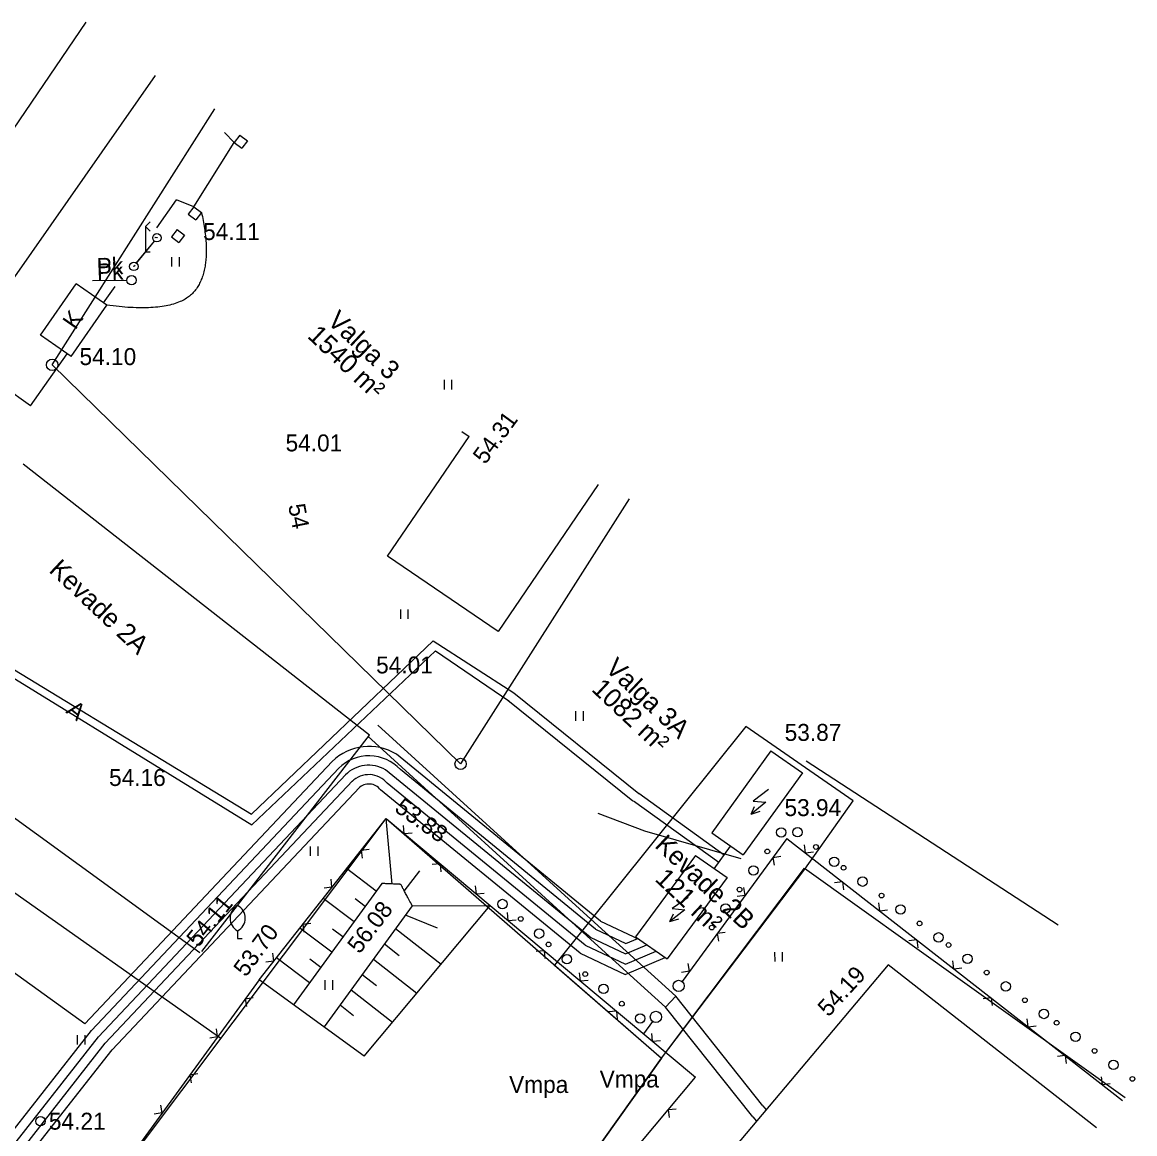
# Model space of a CAD drawing. Extents: x -2270 to -2134, y 846 to 969.
# Drawn here: x -2193 to -2133.9, y 905.2 to 964.2 of the extents above; entities that cross this region are included whole.
import ezdxf

# ---------------------------------------------------------------- set-up
doc = ezdxf.new("R2010")
doc.units = 0
for name, color, linetype in [('Level 10', 7, 'Continuous'), ('Level 12', 7, 'Continuous'), ('Level 15', 7, 'Continuous'), ('Level 19', 7, 'Continuous'), ('Level 21', 7, 'Continuous'), ('Level 32', 7, 'Continuous'), ('Level 4', 7, 'Continuous'), ('Level 45', 7, 'Continuous'), ('Level 6', 7, 'Continuous'), ('Level 63', 7, 'Continuous'), ('Level 7', 7, 'Continuous'), ('Level 8', 7, 'Continuous'), ('Level 9', 7, 'Continuous')]:
    doc.layers.add(name, color=color, linetype=linetype)

# ---------------------------------------------------------------- blocks, each defined once
blk = doc.blocks.new('37')
at = {"layer": 'Level 63'}
blk.add_line((0, 0), (0, 0), dxfattribs=at)
for centre, radius in [((0.0004, 0.2501), 0.005), ((0.0004, 0.2001), 0.01), ((0.0003, 0.1501), 0.005), ((0.0002, 0.1001), 0.01), ((0.0001, 0.05), 0.005), ((0, 0), 0.01)]:
    blk.add_circle(centre, radius, dxfattribs=at)
blk = doc.blocks.new('HAKA')
at = {"layer": 'Level 63'}
for q in [(-0.012, 0.012), (0.012, 0.012)]:
    blk.add_line((0, 0), q, dxfattribs=at)

msp = doc.modelspace()

# ---------------------------------------------------------------- linework, layer by layer
at = {"layer": 'Level 10'}
for p, q in [((-2181.4, 958.241), (-2181.701, 957.842)), ((-2181.4, 958.241), (-2181.001, 957.94)), ((-2181.701, 957.842), (-2181.302, 957.541)), ((-2181.001, 957.94), (-2181.302, 957.541)), ((-2183.838, 954.437), (-2184.139, 954.038)), ((-2183.838, 954.437), (-2183.439, 954.136)), ((-2183.439, 954.136), (-2183.74, 953.737)), ((-2184.139, 954.038), (-2183.74, 953.737)), ((-2184.739, 953.232), (-2185.04, 952.833)), ((-2184.739, 953.232), (-2184.34, 952.931)), ((-2184.34, 952.931), (-2184.641, 952.532)), ((-2185.04, 952.833), (-2184.641, 952.532)), ((-2180.377, 913.395), (-2173.638, 921.957)), ((-2173.638, 921.957), (-2168.115, 917.339)), ((-2172.679, 921.155), (-2172.717, 921.578)), ((-2172.679, 921.155), (-2172.257, 921.193)), ((-2152.352, 920.896), (-2157.922, 913.305)), ((-2152.352, 920.896), (-2134.526, 906.987)), ((-2151.366, 920.127), (-2151.418, 920.548)), ((-2174.965, 920.271), (-2174.544, 920.321)), ((-2174.965, 920.271), (-2174.915, 919.849)), ((-2153.091, 919.888), (-2152.672, 919.953)), ((-2153.091, 919.888), (-2153.027, 919.469)), ((-2151.366, 920.127), (-2150.945, 920.179)), ((-2170.761, 919.552), (-2171.184, 919.514)), ((-2170.761, 919.552), (-2170.724, 919.129)), ((-2176.512, 918.306), (-2176.562, 918.727)), ((-2176.512, 918.306), (-2176.933, 918.256)), ((-2168.843, 917.948), (-2168.881, 918.371)), ((-2154.57, 917.873), (-2154.635, 918.292)), ((-2149.395, 918.589), (-2149.817, 918.537)), ((-2149.395, 918.589), (-2149.344, 918.168)), ((-2168.843, 917.948), (-2168.421, 917.986)), ((-2154.57, 917.873), (-2154.99, 917.808)), ((-2168.115, 917.339), (-2162.369, 912.535)), ((-2167.156, 916.537), (-2167.194, 916.96)), ((-2178.058, 916.342), (-2177.637, 916.392)), ((-2178.058, 916.342), (-2178.008, 915.92)), ((-2167.156, 916.537), (-2166.734, 916.575)), ((-2156.049, 915.857), (-2155.63, 915.922)), ((-2156.049, 915.857), (-2155.985, 915.438)), ((-2179.604, 914.377), (-2179.655, 914.798)), ((-2165.238, 914.934), (-2165.661, 914.896)), ((-2165.238, 914.934), (-2165.201, 914.511)), ((-2179.604, 914.377), (-2180.026, 914.327)), ((-2157.528, 913.842), (-2157.593, 914.261)), ((-2180.377, 913.395), (-2188.744, 901.892)), ((-2163.32, 913.33), (-2163.358, 913.753)), ((-2163.32, 913.33), (-2162.898, 913.368)), ((-2157.528, 913.842), (-2157.948, 913.777)), ((-2181.113, 912.384), (-2180.694, 912.45)), ((-2181.113, 912.384), (-2181.047, 911.965)), ((-2162.369, 912.535), (-2157.213, 908.223)), ((-2161.403, 911.727), (-2161.826, 911.689)), ((-2161.403, 911.727), (-2161.365, 911.304)), ((-2159.483, 911.177), (-2159.963, 910.523)), ((-2182.583, 910.363), (-2182.65, 910.782)), ((-2159.485, 910.123), (-2159.523, 910.545)), ((-2182.583, 910.363), (-2183.003, 910.297)), ((-2159.485, 910.123), (-2159.062, 910.16)), ((-2184.054, 908.341), (-2183.635, 908.407)), ((-2184.054, 908.341), (-2183.988, 907.922)), ((-2162.369, 902.057), (-2157.213, 908.223)), ((-2185.524, 906.319), (-2185.944, 906.253)), ((-2185.524, 906.319), (-2185.591, 906.738))]:
    msp.add_line(p, q, dxfattribs=at)
for centre in [(-2158.1, 913.063), (-2159.306, 911.419)]:
    msp.add_circle(centre, 0.3, dxfattribs=at)
at = {"layer": 'Level 12'}
for p, q in [((-2186.162, 953.636), (-2186.412, 953.385)), ((-2186.412, 953.385), (-2186.413, 952.028)), ((-2186.412, 953.385), (-2186.162, 953.136)), ((-2186.896, 951.451), (-2185.93, 952.605)), ((-2185.817, 952.794), (-2185.907, 952.802)), ((-2186.163, 952.028), (-2186.413, 952.028)), ((-2187.024, 951.278), (-2186.958, 951.339)), ((-2187.4, 950.529), (-2189.222, 950.496))]:
    msp.add_line(p, q, dxfattribs=at)
for centre, radius in [((-2185.907, 952.802), 0.005), ((-2185.807, 952.793), 0.01), ((-2187.031, 951.271), 0.01), ((-2186.958, 951.339), 0.005), ((-2187.15, 950.533), 0.25), ((-2191.993, 905.88), 0.25), ((-2191.993, 905.88), 0.25)]:
    msp.add_circle(centre, radius, dxfattribs=at)
at = {"layer": 'Level 15'}
for p, q in [((-2181.4, 958.241), (-2181.701, 957.842)), ((-2181.4, 958.241), (-2181.001, 957.94)), ((-2181.701, 957.842), (-2181.302, 957.541)), ((-2181.001, 957.94), (-2181.302, 957.541)), ((-2183.838, 954.437), (-2184.139, 954.038)), ((-2183.838, 954.437), (-2183.439, 954.136)), ((-2183.439, 954.136), (-2183.74, 953.737)), ((-2184.139, 954.038), (-2183.74, 953.737)), ((-2184.739, 953.232), (-2185.04, 952.833)), ((-2184.739, 953.232), (-2184.34, 952.931)), ((-2184.34, 952.931), (-2184.641, 952.532)), ((-2185.04, 952.833), (-2184.641, 952.532))]:
    msp.add_line(p, q, dxfattribs=at)
msp.add_lwpolyline([(-2238.128, 896.128), (-2210.494, 933.465), (-2189.567, 964.235)], dxfattribs=at)
at = {"layer": 'Level 19'}
for p, q in [((-2185.903, 961.405), (-2197.926, 944.224)), ((-2174.518, 926.382), (-2192.902, 940.765)), ((-2167.174, 928.244), (-2160.529, 922.892)), ((-2166.861, 928.633), (-2160.215, 923.282)), ((-2183.428, 914.895), (-2174.518, 926.382)), ((-2155.967, 919.609), (-2160.507, 922.876)), ((-2155.675, 920.015), (-2160.215, 923.282)), ((-2156.206, 919.278), (-2155.348, 920.479))]:
    msp.add_line(p, q, dxfattribs=at)
for points in [[(-2197.783, 932.526), (-2180.783, 922.176), (-2171.133, 931.391), (-2166.861, 928.633)], [(-2197.901, 932.165), (-2180.774, 921.614), (-2171.008, 930.85), (-2167.125, 928.209)]]:
    msp.add_lwpolyline(points, dxfattribs=at)
at = {"layer": 'Level 21'}
for p, q in [((-2162.256, 916.501), (-2173.084, 925.363)), ((-2189.64, 911.045), (-2176.503, 924.978)), ((-2189.276, 910.702), (-2176.139, 924.635)), ((-2151.337, 925.021), (-2137.95, 916.314)), ((-2188.912, 910.359), (-2175.776, 924.292)), ((-2162.793, 915.648), (-2173.662, 924.544)), ((-2162.525, 916.075), (-2172.879, 924.549)), ((-2188.549, 910.016), (-2175.412, 923.949)), ((-2188.185, 909.673), (-2175.048, 923.606)), ((-2163.329, 914.795), (-2173.933, 923.474)), ((-2163.061, 915.222), (-2173.575, 923.827)), ((-2189.64, 911.045), (-2200.158, 918.652)), ((-2162.256, 916.501), (-2160.221, 915.551)), ((-2162.525, 916.075), (-2160.908, 915.32)), ((-2163.061, 915.222), (-2160.93, 914.226)), ((-2162.793, 915.648), (-2160.919, 914.773)), ((-2160.919, 914.773), (-2159.788, 915.249)), ((-2160.908, 915.32), (-2160.273, 915.587)), ((-2163.329, 914.795), (-2160.94, 913.679)), ((-2160.94, 913.679), (-2158.81, 914.575)), ((-2160.93, 914.226), (-2159.303, 914.91)), ((-2208.173, 886.648), (-2189.276, 910.702)), ((-2207.864, 886.227), (-2188.912, 910.359)), ((-2207.466, 885.925), (-2188.549, 910.016)), ((-2207.068, 885.622), (-2188.185, 909.673))]:
    msp.add_line(p, q, dxfattribs=at)
for radius, start in [(2.77, 58.03691), (2.27, 42.59346), (1.77, 59.88305), (1.27, 39.85548), (0.77, 36.76007)]:
    msp.add_arc((-2174.55, 923.013), radius, start, 134.82374, dxfattribs=at)
at = {"layer": 'Level 32'}
msp.add_lwpolyline([(-2154.788, 919.816), (-2159.894, 921.281), (-2162.369, 922.212)], dxfattribs=at)
at = {"layer": 'Level 45'}
for p, q in [((-2169.679, 924.854), (-2191.369, 946.044)), ((-2206.455, 927.192), (-2182.404, 910.289)), ((-2154.541, 926.833), (-2164.685, 914.164)), ((-2148.828, 922.892), (-2154.541, 926.833)), ((-2151.398, 919.271), (-2148.828, 922.892)), ((-2195.519, 892.834), (-2173.639, 921.954)), ((-2173.639, 921.954), (-2159.019, 909.234)), ((-2159.019, 909.234), (-2151.409, 919.324)), ((-2159.019, 909.234), (-2151.398, 919.271)), ((-2151.409, 919.324), (-2134.388, 907.134)), ((-2164.685, 914.164), (-2159.019, 909.234)), ((-2159.019, 909.234), (-2173.879, 888.284)), ((-2173.879, 888.284), (-2159.019, 909.234))]:
    msp.add_line(p, q, dxfattribs=at)
msp.add_lwpolyline([(-2160.73, 938.925), (-2169.68, 924.85), (-2191.369, 946.044), (-2182.733, 959.637)], dxfattribs=at)
for centre in [(-2191.369, 946.044), (-2169.679, 924.854)]:
    msp.add_circle(centre, 0.3, dxfattribs=at)
at = {"layer": 'Level 6'}
for p, q in [((-2191.989, 947.614), (-2190.091, 950.35)), ((-2188.47, 949.216), (-2190.091, 950.35)), ((-2190.368, 946.48), (-2188.47, 949.216)), ((-2190.368, 946.48), (-2191.989, 947.614)), ((-2169.608, 942.508), (-2169.223, 942.245)), ((-2173.556, 935.889), (-2169.223, 942.245)), ((-2162.369, 939.685), (-2167.68, 931.887)), ((-2167.68, 931.887), (-2173.556, 935.889)), ((-2153.201, 925.548), (-2156.346, 921.188)), ((-2153.201, 925.548), (-2156.346, 921.188)), ((-2153.201, 925.548), (-2156.346, 921.188)), ((-2153.201, 925.548), (-2156.346, 921.188)), ((-2153.201, 925.548), (-2151.525, 924.378)), ((-2153.201, 925.548), (-2151.525, 924.378)), ((-2153.201, 925.548), (-2151.525, 924.378)), ((-2153.201, 925.548), (-2151.525, 924.378)), ((-2151.525, 924.378), (-2154.67, 920.018)), ((-2151.525, 924.378), (-2154.67, 920.018)), ((-2151.525, 924.378), (-2154.67, 920.018)), ((-2151.525, 924.378), (-2154.67, 920.018)), ((-2153.324, 923.498), (-2154.139, 922.872)), ((-2153.324, 923.498), (-2154.139, 922.872)), ((-2153.324, 923.498), (-2154.139, 922.872)), ((-2153.324, 923.498), (-2154.139, 922.872)), ((-2153.472, 922.83), (-2154.252, 922.189)), ((-2153.472, 922.83), (-2154.252, 922.189)), ((-2153.472, 922.83), (-2154.252, 922.189)), ((-2153.472, 922.83), (-2154.252, 922.189)), ((-2154.139, 922.872), (-2153.472, 922.83)), ((-2154.139, 922.872), (-2153.472, 922.83)), ((-2154.139, 922.872), (-2153.472, 922.83)), ((-2154.139, 922.872), (-2153.472, 922.83)), ((-2154.252, 922.189), (-2154.07, 922.593)), ((-2154.252, 922.189), (-2154.07, 922.593)), ((-2154.252, 922.189), (-2154.07, 922.593)), ((-2154.252, 922.189), (-2154.07, 922.593)), ((-2154.252, 922.189), (-2153.779, 922.338)), ((-2154.252, 922.189), (-2153.779, 922.338)), ((-2154.252, 922.189), (-2153.779, 922.338)), ((-2154.252, 922.189), (-2153.779, 922.338)), ((-2156.346, 921.188), (-2154.67, 920.018)), ((-2156.346, 921.188), (-2154.67, 920.018)), ((-2156.346, 921.188), (-2154.67, 920.018)), ((-2156.346, 921.188), (-2154.67, 920.018)), ((-2157.204, 919.987), (-2160.389, 915.664)), ((-2157.204, 919.987), (-2160.389, 915.664)), ((-2157.204, 919.987), (-2160.389, 915.664)), ((-2157.204, 919.987), (-2160.389, 915.664)), ((-2157.204, 919.987), (-2155.528, 918.817)), ((-2157.204, 919.987), (-2155.528, 918.817)), ((-2157.204, 919.987), (-2155.528, 918.817)), ((-2157.204, 919.987), (-2155.528, 918.817)), ((-2155.528, 918.817), (-2158.713, 914.494)), ((-2155.528, 918.817), (-2158.713, 914.494)), ((-2155.528, 918.817), (-2158.713, 914.494)), ((-2155.528, 918.817), (-2158.713, 914.494)), ((-2157.602, 917.764), (-2158.439, 917.169)), ((-2157.602, 917.764), (-2158.439, 917.169)), ((-2157.602, 917.764), (-2158.439, 917.169)), ((-2157.602, 917.764), (-2158.439, 917.169)), ((-2157.774, 917.103), (-2158.577, 916.49)), ((-2157.774, 917.103), (-2158.577, 916.49)), ((-2157.774, 917.103), (-2158.577, 916.49)), ((-2157.774, 917.103), (-2158.577, 916.49)), ((-2158.577, 916.49), (-2158.381, 916.887)), ((-2158.577, 916.49), (-2158.381, 916.887)), ((-2158.577, 916.49), (-2158.381, 916.887)), ((-2158.577, 916.49), (-2158.381, 916.887)), ((-2158.439, 917.169), (-2157.774, 917.103)), ((-2158.439, 917.169), (-2157.774, 917.103)), ((-2158.439, 917.169), (-2157.774, 917.103)), ((-2158.439, 917.169), (-2157.774, 917.103)), ((-2158.577, 916.49), (-2158.099, 916.621)), ((-2158.577, 916.49), (-2158.099, 916.621)), ((-2158.577, 916.49), (-2158.099, 916.621)), ((-2158.577, 916.49), (-2158.099, 916.621)), ((-2160.389, 915.664), (-2158.713, 914.494)), ((-2160.389, 915.664), (-2158.713, 914.494)), ((-2160.389, 915.664), (-2158.713, 914.494)), ((-2160.389, 915.664), (-2158.713, 914.494))]:
    msp.add_line(p, q, dxfattribs=at)
at = {"layer": 'Level 63'}
for p, q in [((-2149.84, 919.654), (-2149.84, 919.654)), ((-2149.84, 919.654), (-2149.84, 919.654)), ((-2149.84, 919.654), (-2149.84, 919.654)), ((-2149.84, 919.654), (-2149.84, 919.654)), ((-2165.51, 915.841), (-2165.51, 915.841)), ((-2160.144, 911.336), (-2160.144, 911.336))]:
    msp.add_line(p, q, dxfattribs=at)
at = {"layer": 'Level 7'}
for p, q in [((-2181.701, 957.842), (-2182.216, 958.379)), ((-2183.838, 954.437), (-2181.701, 957.842)), ((-2185.818, 953.312), (-2184.761, 954.8)), ((-2183.838, 954.437), (-2184.761, 954.8)), ((-2188.643, 949.337), (-2188.025, 950.207)), ((-2192.525, 943.875), (-2190.572, 946.623)), ((-2192.525, 943.875), (-2193.951, 944.887)), ((-2183.528, 914.813), (-2204.489, 930.045)), ((-2162.369, 916.261), (-2174.073, 926.911)), ((-2162.369, 915.18), (-2174.611, 926.319)), ((-2158.257, 912.52), (-2162.369, 916.261)), ((-2158.796, 911.928), (-2162.369, 915.18)), ((-2146.968, 914.186), (-2157.904, 901.206)), ((-2135.904, 905.524), (-2146.968, 914.186)), ((-2158.257, 912.52), (-2158.796, 911.928)), ((-2153.626, 906.702), (-2158.257, 912.52)), ((-2154.164, 906.11), (-2158.796, 911.928)), ((-2153.626, 906.702), (-2153.453, 906.489)), ((-2154.164, 906.11), (-2153.966, 905.88))]:
    msp.add_line(p, q, dxfattribs=at)
msp.add_open_spline([(-2183.439, 954.136), (-2182.792, 951.215), (-2184.823, 948.705), (-2188.47, 949.216)], degree=2, dxfattribs=at)
at = {"layer": 'Level 8'}
for p, q in [((-2186.162, 953.635), (-2186.412, 953.385)), ((-2186.412, 953.385), (-2186.413, 952.028)), ((-2186.412, 953.385), (-2186.163, 953.135)), ((-2186.897, 951.452), (-2185.93, 952.605)), ((-2186.163, 952.028), (-2186.413, 952.028)), ((-2187.4, 950.529), (-2189.222, 950.496))]:
    msp.add_line(p, q, dxfattribs=at)
for centre, radius in [((-2185.807, 952.793), 0.225), ((-2187.031, 951.271), 0.225), ((-2187.15, 950.533), 0.25), ((-2191.993, 905.88), 0.25)]:
    msp.add_circle(centre, radius, dxfattribs=at)
at = {"layer": 'Level 9'}
for p, q in [((-2185.016, 951.263), (-2185.016, 951.763)), ((-2184.616, 951.263), (-2184.616, 951.763)), ((-2170.543, 944.74), (-2170.543, 945.24)), ((-2170.143, 944.74), (-2170.143, 945.24)), ((-2172.859, 932.556), (-2172.859, 933.056)), ((-2172.459, 932.556), (-2172.459, 933.056)), ((-2163.561, 927.148), (-2163.561, 927.648)), ((-2163.161, 927.148), (-2163.161, 927.648)), ((-2173.309, 918.461), (-2173.638, 921.957)), ((-2152.654, 921.213), (-2152.654, 921.213)), ((-2177.651, 919.968), (-2177.651, 920.468)), ((-2177.251, 919.968), (-2177.251, 920.468)), ((-2174.16, 918.096), (-2175.737, 919.29)), ((-2171.86, 919.17), (-2172.694, 918.088)), ((-2173.865, 918.502), (-2178.547, 912.064)), ((-2175.34, 916.474), (-2176.978, 917.714)), ((-2174.75, 917.285), (-2175.286, 917.691)), ((-2172.247, 917.325), (-2176.93, 910.888)), ((-2174.803, 909.341), (-2168.115, 917.339)), ((-2172.259, 917.31), (-2168.115, 917.339)), ((-2170.9, 916.133), (-2172.608, 916.829)), ((-2181.52, 915.983), (-2181.519, 915.581)), ((-2176.52, 914.852), (-2178.219, 916.138)), ((-2175.93, 915.663), (-2176.486, 916.084)), ((-2173.132, 916.109), (-2170.719, 914.225)), ((-2181.519, 915.581), (-2181.279, 915.581)), ((-2173.722, 915.297), (-2172.936, 914.684)), ((-2177.7, 913.229), (-2179.46, 914.561)), ((-2152.981, 914.358), (-2152.99, 914.858)), ((-2152.581, 914.364), (-2152.59, 914.864)), ((-2177.11, 914.04), (-2177.686, 914.477)), ((-2174.312, 914.486), (-2172.006, 912.686)), ((-2174.803, 909.341), (-2180.377, 913.395)), ((-2176.869, 912.862), (-2176.869, 913.362)), ((-2176.469, 912.862), (-2176.469, 913.362)), ((-2174.902, 913.675), (-2174.151, 913.089)), ((-2175.492, 912.864), (-2173.292, 911.147)), ((-2176.082, 912.053), (-2175.367, 911.495)), ((-2160.144, 911.336), (-2160.144, 911.336)), ((-2190.02, 909.952), (-2190.02, 910.452)), ((-2189.62, 909.952), (-2189.62, 910.452))]:
    msp.add_line(p, q, dxfattribs=at)
for centre, radius in [((-2152.654, 921.213), 0.25), ((-2151.784, 921.228), 0.25), ((-2151.784, 921.228), 0.25), ((-2151.784, 921.228), 0.25), ((-2151.784, 921.228), 0.25), ((-2150.812, 920.441), 0.125), ((-2150.812, 920.441), 0.125), ((-2150.812, 920.441), 0.125), ((-2150.812, 920.441), 0.125), ((-2153.392, 920.203), 0.125), ((-2149.84, 919.654), 0.25), ((-2149.84, 919.654), 0.25), ((-2149.84, 919.654), 0.25), ((-2149.84, 919.654), 0.25), ((-2154.13, 919.193), 0.25), ((-2154.867, 918.183), 0.125), ((-2167.457, 917.412), 0.25), ((-2155.605, 917.173), 0.25), ((-2166.483, 916.626), 0.125), ((-2165.51, 915.84), 0.25), ((-2156.343, 916.163), 0.125), ((-2165.011, 915.264), 0.125), ((-2164.037, 914.478), 0.25), ((-2163.064, 913.692), 0.125), ((-2162.091, 912.907), 0.25), ((-2162.091, 912.907), 0.25), ((-2161.118, 912.121), 0.125), ((-2161.118, 912.121), 0.125), ((-2160.145, 911.336), 0.25), ((-2160.144, 911.336), 0.25), ((-2138.027, 911.105), 0.125), ((-2138.027, 911.105), 0.125), ((-2138.027, 911.105), 0.125), ((-2138.027, 911.105), 0.125), ((-2137.021, 910.361), 0.25), ((-2137.021, 910.361), 0.25), ((-2137.021, 910.361), 0.25), ((-2137.021, 910.361), 0.25), ((-2136.016, 909.616), 0.125), ((-2136.016, 909.616), 0.125), ((-2136.016, 909.616), 0.125), ((-2136.016, 909.616), 0.125), ((-2135.011, 908.872), 0.25), ((-2135.011, 908.872), 0.25), ((-2135.011, 908.872), 0.25), ((-2135.011, 908.872), 0.25), ((-2134.005, 908.128), 0.125), ((-2134.005, 908.128), 0.125), ((-2134.005, 908.128), 0.125), ((-2134.005, 908.128), 0.125)]:
    msp.add_circle(centre, radius, dxfattribs=at)
for centre, start, end in [((-2181.162, 916.658), 118.07128, 242.07104), ((-2181.879, 916.657), 298.07128, 62.07104)]:
    msp.add_arc(centre, 0.763, start, end, dxfattribs=at)
msp.add_open_spline([(-2172.247, 917.325), (-2172.857, 918.456), (-2172.857, 918.456), (-2173.865, 918.502)], degree=2, dxfattribs=at)

# ---------------------------------------------------------------- block references
at = {"layer": 'Level 10', "xscale": 25, "yscale": 25}
for p, rotation in [((-2147.424, 917.051), -37.9647), ((-2145.453, 915.513), 142.03530000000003), ((-2143.482, 913.976), -37.9647), ((-2141.511, 912.438), 142.03530000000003), ((-2139.54, 910.9), -37.9647), ((-2137.569, 909.362), 142.03530000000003), ((-2135.598, 907.824), -37.9647), ((-2158.649, 906.506), -129.90060000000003)]:
    msp.add_blockref('HAKA', p, dxfattribs=dict(at, rotation=rotation))
at = {"layer": 'Level 9', "xscale": 25}
for p, yscale, rotation in [((-2144.3, 915.642), 25, 53.85576208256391), ((-2144.3, 915.642), 25, 53.85576208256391), ((-2144.3, 915.642), 25, 53.85576208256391), ((-2144.3, 915.642), 25, 53.85576208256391), ((-2138.703, 911.574), 24.999999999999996, 54.23280976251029), ((-2138.703, 911.574), 24.999999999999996, 54.23280976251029), ((-2138.703, 911.574), 24.999999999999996, 54.23280976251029), ((-2138.703, 911.574), 24.999999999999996, 54.23280976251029)]:
    msp.add_blockref('37', p, dxfattribs=dict(at, yscale=yscale, rotation=rotation))

# ---------------------------------------------------------------- texts
at = {"layer": 'Level 12'}
msp.add_text('Pk', height=0.9, rotation=2, dxfattribs=at).set_placement((-2188.988, 950.811))
at = {"layer": 'Level 32'}
msp.add_text('54', height=0.9, rotation=281, dxfattribs=at).set_placement((-2178.841, 938.581))
at = {"layer": 'Level 4'}
for s, p in [('54.11', (-2183.355, 952.672)), ('54.10', (-2189.918, 946.03)), ('54.01', (-2178.976, 941.448)), ('54.01', (-2174.167, 929.656)), ('53.87', (-2152.472, 926.076)), ('54.16', (-2188.348, 923.681)), ('53.94', (-2152.481, 922.081)), ('54.21', (-2191.543, 905.43)), ('54.21', (-2191.543, 905.43))]:
    msp.add_text(s, height=0.9, dxfattribs=at).set_placement(p)
for s, height, rotation, p in [('54.31', 0.9, 53.81677, (-2168.371, 940.711)), ('53.88', 0.9, 324.53746, (-2173.242, 922.375)), ('54.11', 0.8995, 51.15952, (-2183.613, 915.064)), ('56.08', 0.8995, 52.80976, (-2175.048, 914.723)), ('53.70', 0.9, 53.62099, (-2181.084, 913.491)), ('54.19', 0.9, 47.37433, (-2150.144, 911.377))]:
    msp.add_text(s, height=height, rotation=rotation, dxfattribs=at).set_placement(p)
at = {"layer": 'Level 45'}
for s, p in [('Valga 3', (-2176.808, 948.295)), ('1540 m²', (-2177.867, 947.522)), ('Kevade 2A', (-2191.589, 935.084)), ('Valga 3A', (-2162.05, 929.848)), ('1082 m²', (-2162.776, 928.76)), ('Kevade 2B', (-2159.419, 920.461)), ('121 m²', (-2159.412, 918.683))]:
    msp.add_text(s, height=1, rotation=316.73027, dxfattribs=at).set_placement(p)
at = {"layer": 'Level 6'}
msp.add_text('K', height=0.899, rotation=55.23744, dxfattribs=at).set_placement((-2190.139, 947.865))
at = {"layer": 'Level 7'}
msp.add_text('A', height=0.9, rotation=321.6993, dxfattribs=at).set_placement((-2190.678, 927.595))
at = {"layer": 'Level 8'}
msp.add_text('Pk', height=0.9, rotation=2.56173, dxfattribs=at).set_placement((-2188.977, 950.511))
at = {"layer": 'Level 9'}
for p in [(-2167.105, 907.38), (-2162.295, 907.669)]:
    msp.add_text('Vmpa', height=0.9, dxfattribs=at).set_placement(p)

doc.saveas('drawing.dxf')
